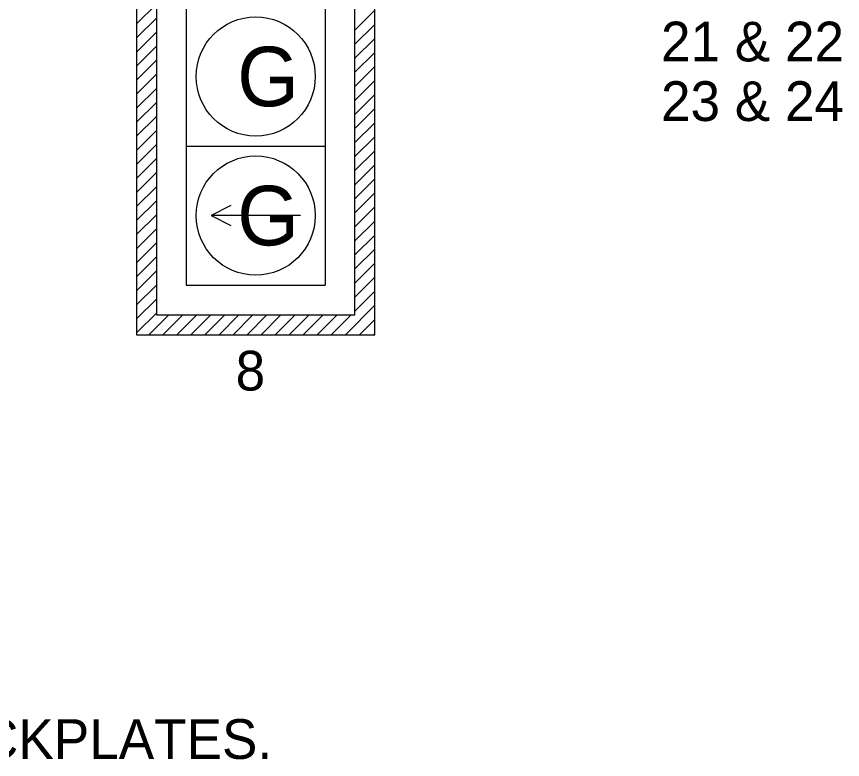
# Model space of a CAD drawing. Extents: x 662183 to 663183, y 642099 to 642739.
# Drawn here: x 662340.9 to 662424.1, y 642585.8 to 642660.6 of the extents above; entities that cross this region are included whole.
import ezdxf

# ---------------------------------------------------------------- set-up
doc = ezdxf.new("R2010")
doc.units = 0
doc.layers.add('Default', color=7, linetype='Continuous')
doc.layers.add('T_Drafting', color=7, linetype='Continuous')

msp = doc.modelspace()

# ---------------------------------------------------------------- linework, layer by layer
at = {"layer": 'T_Drafting'}
for p, q in [((662352.987, 642694.563), (662352.987, 642628.563)), ((662376.987, 642628.563), (662376.987, 642694.563)), ((662352.987, 642659.857), (662354.987, 642661.857)), ((662357.987, 642661.563), (662357.987, 642647.563)), ((662371.987, 642661.563), (662371.987, 642647.563)), ((662374.987, 642659.23), (662376.987, 642661.23)), ((662352.987, 642658.443), (662354.987, 642660.443)), ((662352.987, 642657.029), (662354.987, 642659.029)), ((662374.987, 642657.815), (662376.987, 642659.815)), ((662374.987, 642656.401), (662376.987, 642658.401)), ((662352.987, 642655.614), (662354.987, 642657.614)), ((662374.987, 642654.987), (662376.987, 642656.987)), ((662352.987, 642654.2), (662354.987, 642656.2)), ((662374.987, 642653.573), (662376.987, 642655.573)), ((662352.987, 642652.786), (662354.987, 642654.786)), ((662374.987, 642652.158), (662376.987, 642654.158)), ((662352.987, 642651.372), (662354.987, 642653.372)), ((662374.987, 642650.744), (662376.987, 642652.744)), ((662352.987, 642649.957), (662354.987, 642651.957)), ((662374.987, 642649.33), (662376.987, 642651.33)), ((662352.987, 642648.543), (662354.987, 642650.543)), ((662374.987, 642647.916), (662376.987, 642649.916)), ((662352.987, 642647.129), (662354.987, 642649.129)), ((662374.987, 642646.502), (662376.987, 642648.502)), ((662352.987, 642645.715), (662354.987, 642647.715)), ((662357.987, 642647.563), (662371.987, 642647.563)), ((662357.987, 642647.563), (662357.987, 642633.563)), ((662371.987, 642647.563), (662371.987, 642633.563)), ((662374.987, 642645.087), (662376.987, 642647.087)), ((662352.987, 642644.301), (662354.987, 642646.301)), ((662352.987, 642642.886), (662354.987, 642644.886)), ((662374.987, 642643.673), (662376.987, 642645.673)), ((662374.987, 642642.259), (662376.987, 642644.259)), ((662352.987, 642641.472), (662354.987, 642643.472)), ((662374.987, 642640.845), (662376.987, 642642.845)), ((662352.987, 642640.058), (662354.987, 642642.058)), ((662374.987, 642639.431), (662376.987, 642641.431)), ((662352.987, 642638.644), (662354.987, 642640.644)), ((662369.487, 642640.563), (662360.487, 642640.563)), ((662374.987, 642638.016), (662376.987, 642640.016)), ((662352.987, 642637.23), (662354.987, 642639.23)), ((662374.987, 642636.602), (662376.987, 642638.602)), ((662352.987, 642635.815), (662354.987, 642637.815)), ((662374.987, 642635.188), (662376.987, 642637.188)), ((662352.987, 642634.401), (662354.987, 642636.401)), ((662374.987, 642633.774), (662376.987, 642635.774)), ((662352.987, 642632.987), (662354.987, 642634.987)), ((662374.987, 642632.359), (662376.987, 642634.359)), ((662352.987, 642631.573), (662354.987, 642633.573)), ((662357.987, 642633.563), (662371.987, 642633.563)), ((662374.987, 642630.945), (662376.987, 642632.945)), ((662352.987, 642630.158), (662354.987, 642632.158)), ((662352.987, 642628.744), (662354.987, 642630.744)), ((662374.018, 642628.563), (662376.987, 642631.531)), ((662354.219, 642628.563), (662356.219, 642630.563)), ((662355.634, 642628.563), (662357.634, 642630.563)), ((662357.048, 642628.563), (662359.048, 642630.563)), ((662358.462, 642628.563), (662360.462, 642630.563)), ((662359.876, 642628.563), (662361.876, 642630.563)), ((662361.29, 642628.563), (662363.29, 642630.563)), ((662362.705, 642628.563), (662364.705, 642630.563)), ((662364.119, 642628.563), (662366.119, 642630.563)), ((662365.533, 642628.563), (662367.533, 642630.563)), ((662366.947, 642628.563), (662368.947, 642630.563)), ((662368.361, 642628.563), (662370.361, 642630.563)), ((662369.776, 642628.563), (662371.776, 642630.563)), ((662371.19, 642628.563), (662373.19, 642630.563)), ((662372.604, 642628.563), (662374.604, 642630.563)), ((662375.432, 642628.563), (662376.987, 642630.117)), ((662352.987, 642628.563), (662376.987, 642628.563)), ((662376.847, 642628.563), (662376.987, 642628.703))]:
    msp.add_line(p, q, dxfattribs=at)
msp.add_lwpolyline([(662374.987, 642692.563), (662354.987, 642692.563), (662354.987, 642630.563), (662374.987, 642630.563)], close=True, dxfattribs=at)
msp.add_lwpolyline([(662362.487, 642641.563), (662360.487, 642640.563), (662362.487, 642639.563)], dxfattribs=at)
for centre in [(662364.987, 642654.563), (662364.987, 642640.563)]:
    msp.add_circle(centre, 6, dxfattribs=at)

# ---------------------------------------------------------------- texts
at = {"layer": 'Default'}
for s, p in [('21 & 22', (662405.819, 642656.086)), ('23 & 24', (662405.819, 642650.086)), ('8', (662362.965, 642622.953)), ('1. ALL SIGNAL HEADS SHALL HAVE BACKPLATES.', (662237.622, 642585.863))]:
    msp.add_text(s, height=4, dxfattribs=at).set_placement(p)
at = {"layer": 'T_Drafting'}
for p in [(662363.121, 642651.564), (662363.121, 642637.564)]:
    msp.add_text('G', height=5.998, dxfattribs=at).set_placement(p)

doc.saveas('drawing.dxf')
